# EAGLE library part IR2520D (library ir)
ADAPTIVE BALLAST CONTROL IC The IR2520D(S) is a complete adaptive ballast controller and 600V half-bridge driver integrated into a single IC for fluorescent lighting applications. Data Sheet No. PD60212 Rev A Source: www.irf.com .. ir2520.pdf
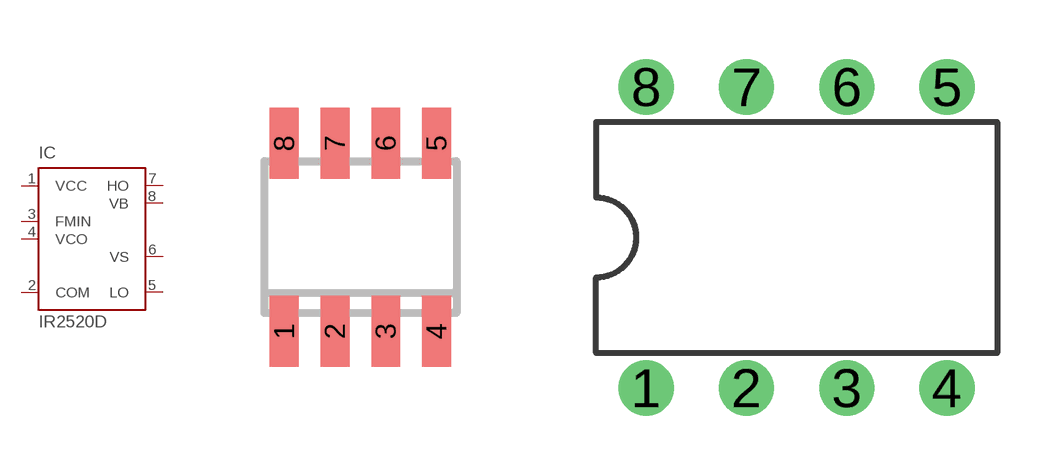
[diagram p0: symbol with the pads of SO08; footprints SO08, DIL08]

Designator prefix IC

## IR2520DS (MF: INTERNATIONAL RECTIFIER(IR); MPN: IR2520DS; OC_FARNELL: 1080634; OC_NEWARK: 63J7917)  [SO08]
1  VCC  pwr
2  COM  pwr
3  FMIN  in
4  VCO  in
5  LO  out
6  VS  in
7  HO  out
8  VB  pas

## IR2520D (MF: INTERNATIONAL RECTIFIER(IR); MPN: IR2520DPBF; OC_FARNELL: 1080633; OC_NEWARK: 63J7916)  [DIL08]
Pads as for SO08

## Footprint SO08 (pad centres in mm)
8 Lead SOIC Data Sheet No. PD60212 Rev A Source: www.irf.com .. ir2520.pdf
smd 0.72 x 1.78: 1 -1.905,-2.35; 2 -0.635,-2.35; 3 0.635,-2.35; 4 1.905,-2.35; 5 1.905,2.35; 6 0.635,2.35; 7 -0.635,2.35; 8 -1.905,2.35

## Footprint DIL08 (pad centres in mm)
Dual In Line Package
drill 0.8 pad 1.4 round: 1 -3.81,-3.81; 2 -1.27,-3.81; 3 1.27,-3.81; 4 3.81,-3.81; 5 3.81,3.81; 6 1.27,3.81; 7 -1.27,3.81; 8 -3.81,3.81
